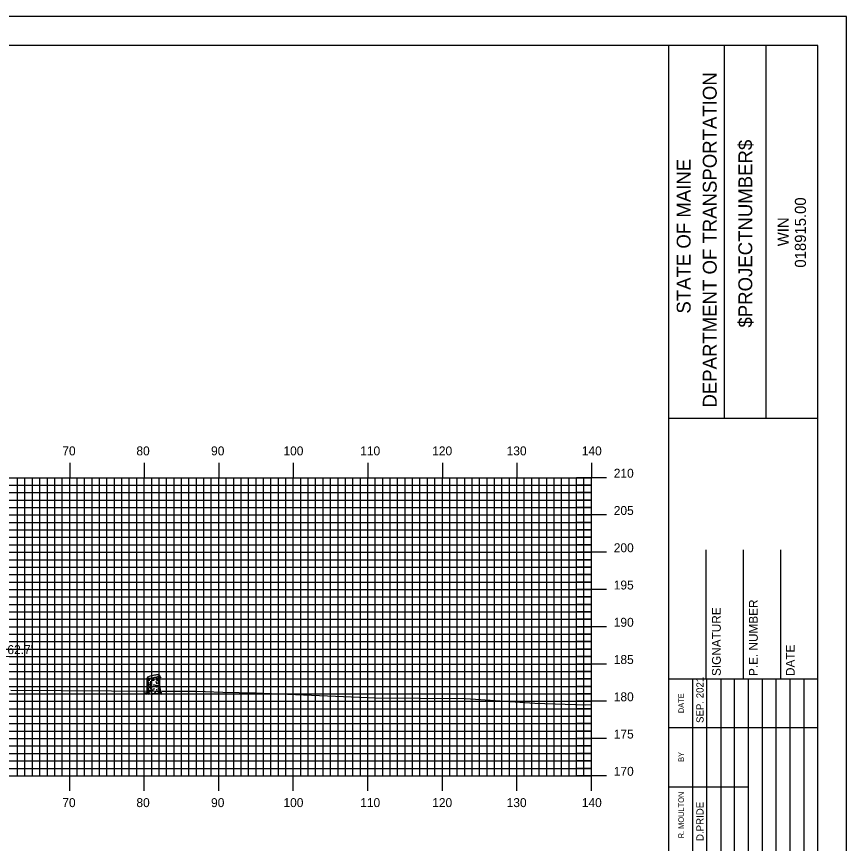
# Model space of a CAD drawing. Extents: x 1808619 to 1808962, y 442591 to 442811.
# Drawn here: x 1808847.7 to 1808959, y 442699.6 to 442810.5 of the extents above; entities that cross this region are included whole.
import ezdxf

# ---------------------------------------------------------------- set-up
doc = ezdxf.new("R2010")
doc.units = 0
for name, color, linetype in [('BORDER', 7, 'Continuous'), ('D_Text_Standard', 7, 'Continuous'), ('H_V ANNOTATION', 7, 'Continuous'), ('M_Trees_Conifer_Pay', 7, 'Continuous'), ('MAJOR', 7, 'Continuous'), ('MINOR', 7, 'Continuous'), ('PLOT BOUNDARY', 7, 'Continuous'), ('S_Roadway_Centerline', 7, 'Continuous')]:
    doc.layers.add(name, color=color, linetype=linetype)

msp = doc.modelspace()

# ---------------------------------------------------------------- linework, layer by layer
at = {"layer": 'BORDER'}
for p, q in [((1808935.21, 442596.67), (1808935.21, 442806.67)), ((1808942.67, 442756.66), (1808942.67, 442806.66)), ((1808948.26, 442756.66), (1808948.26, 442806.66)), ((1808935.21, 442756.65), (1808955.21, 442756.65)), ((1808940.21, 442721.67), (1808940.21, 442738.97)), ((1808945.21, 442721.67), (1808945.21, 442738.97)), ((1808950.21, 442721.67), (1808950.21, 442738.97)), ((1808935.21, 442721.67), (1808955.21, 442721.67))]:
    msp.add_line(p, q, dxfattribs=at)
msp.add_lwpolyline([(1808635.21, 442596.67), (1808955.21, 442596.67), (1808955.21, 442806.67), (1808635.21, 442806.67)], close=True, dxfattribs=at)
for points in [[(1808938.44, 442715.17), (1808938.44, 442721.67)], [(1808940.31, 442686.68), (1808940.31, 442721.67)], [(1808942.17, 442721.67), (1808942.17, 442686.68)], [(1808944.03, 442686.68), (1808944.03, 442721.67)], [(1808945.9, 442686.68), (1808945.9, 442721.67)], [(1808947.76, 442686.68), (1808947.76, 442721.67)], [(1808949.62, 442686.68), (1808949.62, 442721.67)], [(1808951.49, 442686.68), (1808951.49, 442721.67)], [(1808953.35, 442686.68), (1808953.35, 442721.67)], [(1808938.44, 442686.68), (1808938.44, 442720.26)], [(1808935.21, 442715.17), (1808955.21, 442715.17)], [(1808935.21, 442707.17), (1808938.44, 442707.17)], [(1808938.44, 442707.17), (1808945.89, 442707.17)]]:
    msp.add_lwpolyline(points, dxfattribs=at)
at = {"layer": 'M_Trees_Conifer_Pay'}
for p, q in [((1808866.82, 442722.09), (1808866.82, 442721.93)), ((1808866.89, 442720.52), (1808866.89, 442722.16)), ((1808865.22, 442720.11), (1808865.22, 442721.83)), ((1808865.27, 442721.79), (1808865.27, 442721.32)), ((1808865.27, 442721.25), (1808865.27, 442720.95)), ((1808865.33, 442721.78), (1808865.33, 442721.68)), ((1808865.33, 442721.61), (1808865.33, 442721.4)), ((1808865.33, 442721.34), (1808865.33, 442721.15)), ((1808865.33, 442721.1), (1808865.33, 442720.76)), ((1808865.45, 442721.77), (1808865.45, 442721.54)), ((1808865.45, 442721.5), (1808865.45, 442721.42)), ((1808865.45, 442721.02), (1808865.45, 442720.88)), ((1808865.67, 442721.79), (1808865.67, 442721.62)), ((1808865.67, 442721.39), (1808865.67, 442721.15)), ((1808866.08, 442721.56), (1808866.08, 442721.46)), ((1808866.47, 442721.83), (1808866.47, 442721.63)), ((1808866.47, 442721.58), (1808866.47, 442721.49)), ((1808866.47, 442721.14), (1808866.47, 442721.03)), ((1808866.7, 442722.03), (1808866.7, 442721.81)), ((1808866.7, 442721.72), (1808866.7, 442721.67)), ((1808866.76, 442721.53), (1808866.7, 442721.47)), ((1808866.7, 442721.33), (1808866.7, 442721.2)), ((1808866.7, 442721.09), (1808866.7, 442720.98)), ((1808866.82, 442721.86), (1808866.82, 442721.73)), ((1808866.82, 442721.54), (1808866.82, 442721.21)), ((1808866.82, 442721.17), (1808866.82, 442721.01)), ((1808866.82, 442720.96), (1808866.82, 442720.75)), ((1808865.27, 442720.9), (1808865.27, 442720.41)), ((1808865.27, 442720.35), (1808865.27, 442720.11)), ((1808865.33, 442720.71), (1808865.33, 442720.57)), ((1808865.33, 442720.47), (1808865.33, 442720.1)), ((1808865.45, 442720.61), (1808865.45, 442720.47)), ((1808865.45, 442720.21), (1808865.45, 442720.11)), ((1808865.67, 442720.9), (1808865.67, 442720.75)), ((1808865.67, 442720.71), (1808865.67, 442720.54)), ((1808865.67, 442720.26), (1808865.67, 442720.11)), ((1808866.08, 442720.95), (1808866.08, 442720.87)), ((1808866.08, 442720.85), (1808866.08, 442720.7)), ((1808866.08, 442720.41), (1808866.08, 442720.25)), ((1808866.47, 442720.67), (1808866.47, 442720.52)), ((1808866.47, 442720.29), (1808866.47, 442720.2)), ((1808866.7, 442720.85), (1808866.7, 442720.7)), ((1808866.7, 442720.48), (1808866.7, 442720.31)), ((1808866.82, 442720.71), (1808866.82, 442720.64)), ((1808866.82, 442720.6), (1808866.82, 442720.43)), ((1808865.45, 442719.71), (1808865.62, 442719.78)), ((1808865.89, 442719.65), (1808865.77, 442719.71))]:
    msp.add_line(p, q, dxfattribs=at)
for points in [[(1808865.4, 442721.13), (1808865.4, 442721.23), (1808865.44, 442721.2), (1808865.44, 442721.11)], [(1808866.67, 442721.62), (1808866.64, 442721.54), (1808866.64, 442721.47), (1808866.67, 442721.41)], [(1808866.7, 442721.66), (1808866.74, 442721.59), (1808866.79, 442721.64), (1808866.85, 442721.71), (1808866.94, 442721.9), (1808867, 442721.95), (1808867.03, 442721.96)], [(1808866.72, 442721.41), (1808866.76, 442721.53), (1808866.82, 442721.65), (1808866.85, 442721.72), (1808866.92, 442721.86)], [(1808866.93, 442721.89), (1808867.01, 442721.9), (1808867.08, 442721.8)], [(1808866.89, 442720.52), (1808866.94, 442720.25), (1808866.96, 442719.98), (1808867.01, 442719.85), (1808867.15, 442719.82), (1808866.92, 442719.79), (1808866.92, 442719.79), (1808866.92, 442719.74), (1808867.17, 442719.64), (1808866.9, 442719.66), (1808866.54, 442719.68), (1808866.22, 442719.67), (1808866.23, 442719.75), (1808866.08, 442719.67), (1808865.89, 442719.65), (1808865.92, 442719.58), (1808865.65, 442719.62), (1808865.43, 442719.6), (1808865.14, 442719.61), (1808865.42, 442719.67), (1808865.45, 442719.71), (1808865.29, 442719.77), (1808865.06, 442719.78), (1808864.81, 442719.78), (1808865.16, 442719.84), (1808865.2, 442719.92), (1808865.22, 442720.11)], [(1808865.27, 442720.06), (1808865.25, 442719.98), (1808865.23, 442719.89)], [(1808865.35, 442720.04), (1808865.36, 442719.92), (1808865.3, 442719.83), (1808865.29, 442719.77)], [(1808865.51, 442720.06), (1808865.51, 442719.93), (1808865.42, 442719.83)], [(1808865.74, 442719.82), (1808865.81, 442719.92), (1808865.83, 442720.06)], [(1808866.23, 442719.75), (1808866.3, 442719.9), (1808866.31, 442720)], [(1808866.48, 442720.12), (1808866.49, 442720), (1808866.56, 442719.95)], [(1808866.54, 442720.73), (1808866.55, 442720.66), (1808866.6, 442720.67), (1808866.59, 442720.83)], [(1808866.76, 442719.73), (1808866.74, 442719.87), (1808866.67, 442720)], [(1808866.71, 442720.23), (1808866.79, 442720.12), (1808866.79, 442719.95), (1808866.92, 442719.79)], [(1808866.81, 442720.37), (1808866.82, 442720.23), (1808866.87, 442720.16), (1808866.88, 442719.96)]]:
    msp.add_lwpolyline(points, dxfattribs=at)
for centre, radius, start, end in [((1808867.08, 442717.06), 5.18, 101.7194, 108.0594), ((1808867.08, 442717.06), 5.18, 95.3794, 101.7194), ((1808866.67, 442721.42), 0.802, 79.2194, 95.3794), ((1808866.39, 442722.77), 0.802, 288.0594, 304.2194), ((1808866.77, 442721.96), 0.251, 71.0501, 79.2194), ((1808866.7, 442722.31), 0.251, 304.2194, 312.3887), ((1808866.83, 442722.12), 0.0817, 56.7194, 71.0501), ((1808866.84, 442722.14), 0.0527, 46.923, 56.7194), ((1808866.81, 442722.19), 0.0817, 312.3887, 326.7194), ((1808866.86, 442722.16), 0.0264, 23.4074, 34.2194), ((1808866.86, 442722.16), 0.0314, 34.2194, 46.923), ((1808866.84, 442722.17), 0.0527, 326.7194, 336.5158), ((1808866.87, 442722.16), 0.0226, 11.7194, 23.4074), ((1808866.87, 442722.16), 0.0226, 0.0315, 11.7194), ((1808866.86, 442722.16), 0.0314, 336.5158, 349.2194), ((1808866.86, 442722.16), 0.0264, 349.2194, 0.0315), ((1808865.26, 442721.83), 0.0314, 156.5158, 169.2194), ((1808865.25, 442721.83), 0.0264, 169.2194, 180.0315), ((1808865.25, 442721.83), 0.0226, 180.0315, 191.7194), ((1808865.25, 442721.83), 0.0226, 191.7194, 203.4074), ((1808865.26, 442721.65), 0.0334, 163.9485, 180), ((1808865.26, 442721.65), 0.0334, 180, 196.0515), ((1808865.27, 442721.65), 0.0441, 196.0515, 210), ((1808865.26, 442721.2), 0.0334, 163.9485, 180), ((1808865.26, 442721.2), 0.0334, 180, 196.0515), ((1808865.27, 442721.2), 0.0441, 196.0515, 210), ((1808865.26, 442720.99), 0.0334, 163.9485, 180), ((1808865.26, 442720.99), 0.0334, 180, 196.0515), ((1808865.27, 442720.99), 0.0441, 196.0515, 210), ((1808865.3, 442721.8), 0.0817, 132.3887, 146.7194), ((1808865.27, 442721.82), 0.0527, 146.7194, 156.5158), ((1808865.25, 442721.83), 0.0264, 203.4074, 214.2194), ((1808865.25, 442721.83), 0.0314, 214.2194, 226.923), ((1808865.27, 442721.85), 0.0527, 226.923, 236.7194), ((1808865.28, 442721.66), 0.0624, 210, 228.7494), ((1808865.28, 442721.21), 0.0624, 210, 228.7494), ((1808865.28, 442721), 0.0624, 210, 228.7494), ((1808865.41, 442721.68), 0.251, 124.2194, 132.3887), ((1808865.28, 442721.87), 0.0817, 236.7194, 251.0501), ((1808865.35, 442721.74), 0.172, 228.7494, 240), ((1808865.35, 442721.3), 0.172, 228.7494, 240), ((1808865.35, 442721.09), 0.172, 228.7494, 240), ((1808865.34, 442722.03), 0.251, 251.0501, 259.2194), ((1808865.72, 442721.22), 0.802, 108.0594, 124.2194), ((1808865.55, 442722.09), 0.571, 240, 240.3367), ((1808865.56, 442721.88), 0.571, 240, 247.0587), ((1808865.55, 442721.64), 0.571, 240, 240.3367), ((1808865.44, 442722.57), 0.802, 259.2194, 275.3794), ((1808865.55, 442722.09), 0.571, 246.8597, 257.9846), ((1808865.03, 442726.93), 5.18, 275.3794, 281.7194), ((1808866.05, 442725.16), 4.12, 264.081, 266.6676), ((1808866.06, 442725.84), 4.12, 264.6955, 266.7331), ((1808866.05, 442725.61), 4.12, 268.0751, 270), ((1808866.05, 442725.61), 4.12, 270, 270.3581), ((1808865.03, 442726.93), 5.18, 281.7194, 288.0594), ((1808866.06, 442725.39), 4.12, 273.7052, 275.9504), ((1808866.05, 442725.61), 4.12, 275.7849, 277.0558), ((1808866.06, 442725.84), 4.12, 276.238, 278.1032), ((1808866.05, 442725.16), 4.12, 277.6125, 278.1032), ((1808866.56, 442722.32), 0.571, 278.1032, 284.3667), ((1808866.56, 442721.64), 0.571, 278.1032, 286.9296), ((1808866.56, 442722.48), 0.571, 284.4317, 292.4132), ((1808866.56, 442721.88), 0.571, 284.4493, 297.0429), ((1808866.56, 442722.32), 0.571, 297.0237, 300), ((1808866.56, 442721.64), 0.571, 297.1896, 300), ((1808866.76, 442722.13), 0.172, 300, 311.2506), ((1808866.76, 442721.98), 0.172, 300, 311.2506), ((1808866.75, 442721.3), 0.172, 300, 311.2506), ((1808866.75, 442721.09), 0.172, 300, 311.2506), ((1808866.83, 442722.05), 0.0624, 311.2506, 330), ((1808866.83, 442721.89), 0.0624, 311.2506, 330), ((1808866.83, 442721.21), 0.0624, 311.2506, 330), ((1808866.83, 442721), 0.0624, 311.2506, 330), ((1808866.84, 442722.04), 0.0441, 330, 343.9485), ((1808866.84, 442721.88), 0.0441, 330, 343.9485), ((1808866.84, 442721.2), 0.0441, 330, 343.9485), ((1808866.84, 442720.99), 0.0441, 330, 343.9485), ((1808866.85, 442722.04), 0.0334, 343.9485, 354.2151), ((1808866.85, 442721.88), 0.0334, 343.9485, 354.2151), ((1808866.85, 442721.44), 0.0334, 343.9485, 354.2151), ((1808866.85, 442721.2), 0.0334, 343.9485, 354.2151), ((1808866.85, 442720.99), 0.0334, 343.9485, 354.2151), ((1808865.26, 442720.76), 0.0334, 163.9485, 180), ((1808865.26, 442720.76), 0.0334, 180, 196.0515), ((1808865.27, 442720.76), 0.0441, 196.0515, 210), ((1808865.26, 442720.56), 0.0334, 163.9485, 180), ((1808865.26, 442720.36), 0.0334, 163.9485, 180), ((1808865.26, 442720.36), 0.0334, 180, 196.0515), ((1808865.27, 442720.36), 0.0441, 196.0515, 210), ((1808865.26, 442720.14), 0.0334, 163.9485, 180), ((1808865.26, 442720.14), 0.0334, 180, 196.0515), ((1808865.27, 442720.14), 0.0441, 196.0515, 210), ((1808865.28, 442720.77), 0.0624, 210, 228.7494), ((1808865.28, 442720.37), 0.0624, 210, 228.7494), ((1808865.28, 442720.15), 0.0624, 210, 228.7494), ((1808865.35, 442720.85), 0.172, 228.7494, 240), ((1808865.35, 442720.46), 0.172, 228.7494, 240), ((1808865.35, 442720.24), 0.172, 228.7494, 240), ((1808865.55, 442721.43), 0.571, 240, 246.8597), ((1808865.55, 442721.19), 0.571, 240, 246.8597), ((1808865.54, 442721), 0.571, 241.2369, 248.0268), ((1808865.55, 442720.8), 0.571, 240, 246.8597), ((1808865.55, 442720.58), 0.571, 240, 244.5314), ((1808865.55, 442721.43), 0.571, 259.2707, 261.8968), ((1808866.05, 442724.95), 4.12, 261.8968, 263.1474), ((1808866.05, 442724.1), 4.12, 262.4438, 263.512), ((1808866.05, 442724.51), 4.12, 263.4991, 265.8397), ((1808866.05, 442724.71), 4.12, 264.716, 266.3193), ((1808866.05, 442724.32), 4.12, 267.8117, 270), ((1808866.05, 442724.95), 4.12, 270, 270.3581), ((1808866.05, 442724.32), 4.12, 270, 270.1328), ((1808866.05, 442724.95), 4.12, 273.1493, 275.4569), ((1808866.05, 442724.32), 4.12, 275.7849, 276.7896), ((1808866.05, 442724.1), 4.12, 277.3684, 278.1032), ((1808866.56, 442720.58), 0.571, 278.1032, 281.637), ((1808866.56, 442721.19), 0.571, 285.3983, 297.1896), ((1808866.56, 442721), 0.571, 289.2907, 300), ((1808866.56, 442720.8), 0.571, 288.5067, 297.2721), ((1808866.56, 442721.43), 0.571, 297.1896, 300), ((1808866.75, 442720.65), 0.172, 300, 311.2506), ((1808866.75, 442720.24), 0.172, 300, 311.2506), ((1808866.83, 442720.57), 0.0624, 311.2506, 330), ((1808866.83, 442720.15), 0.0624, 311.2506, 330), ((1808866.84, 442720.56), 0.0441, 330, 343.9485), ((1808866.84, 442720.14), 0.0441, 330, 343.9485), ((1808866.85, 442720.56), 0.0334, 343.9485, 354.2151), ((1808866.85, 442720.14), 0.0334, 343.9485, 354.2151)]:
    msp.add_arc(centre, radius, start, end, dxfattribs=at)
at = {"layer": 'MAJOR'}
for p, q in [((1808854.81, 442750.67), (1808854.81, 442748.67)), ((1808864.81, 442750.67), (1808864.81, 442748.67)), ((1808874.81, 442750.67), (1808874.81, 442748.67)), ((1808884.81, 442750.67), (1808884.81, 442748.67)), ((1808894.81, 442750.67), (1808894.81, 442748.67)), ((1808904.81, 442750.67), (1808904.81, 442748.67)), ((1808914.81, 442750.67), (1808914.81, 442748.67)), ((1808924.81, 442750.67), (1808924.81, 442748.67)), ((1808644.81, 442748.67), (1808924.81, 442748.67)), ((1808644.81, 442748.67), (1808924.81, 442748.67)), ((1808854.81, 442708.67), (1808854.81, 442748.67)), ((1808864.81, 442708.67), (1808864.81, 442748.67)), ((1808874.81, 442708.67), (1808874.81, 442748.67)), ((1808884.81, 442708.67), (1808884.81, 442748.67)), ((1808894.81, 442708.67), (1808894.81, 442748.67)), ((1808904.81, 442708.67), (1808904.81, 442748.67)), ((1808914.81, 442708.67), (1808914.81, 442748.67)), ((1808926.82, 442748.67), (1808922.81, 442748.67)), ((1808924.81, 442708.67), (1808924.81, 442748.67)), ((1808924.81, 442708.67), (1808924.81, 442748.67)), ((1808644.81, 442743.67), (1808924.81, 442743.67)), ((1808926.82, 442743.67), (1808922.81, 442743.67)), ((1808644.81, 442738.67), (1808924.81, 442738.67)), ((1808926.82, 442738.67), (1808922.81, 442738.67)), ((1808644.81, 442733.67), (1808924.81, 442733.67)), ((1808926.82, 442733.67), (1808922.81, 442733.67)), ((1808644.81, 442728.67), (1808924.81, 442728.67)), ((1808926.82, 442728.67), (1808922.81, 442728.67)), ((1808644.81, 442723.67), (1808924.81, 442723.67)), ((1808926.82, 442723.67), (1808922.81, 442723.67)), ((1808644.81, 442718.67), (1808924.81, 442718.67)), ((1808926.82, 442718.67), (1808922.81, 442718.67)), ((1808644.81, 442713.67), (1808924.81, 442713.67)), ((1808926.82, 442713.67), (1808922.81, 442713.67)), ((1808644.81, 442708.67), (1808924.81, 442708.67)), ((1808644.81, 442708.67), (1808924.81, 442708.67)), ((1808854.81, 442706.66), (1808854.81, 442708.67)), ((1808864.81, 442706.66), (1808864.81, 442708.67)), ((1808874.81, 442706.66), (1808874.81, 442708.67)), ((1808884.81, 442706.66), (1808884.81, 442708.67)), ((1808894.81, 442706.66), (1808894.81, 442708.67)), ((1808904.81, 442706.66), (1808904.81, 442708.67)), ((1808914.81, 442706.66), (1808914.81, 442708.67)), ((1808926.82, 442708.67), (1808922.81, 442708.67)), ((1808924.81, 442706.66), (1808924.81, 442708.67))]:
    msp.add_line(p, q, dxfattribs=at)
at = {"layer": 'MINOR'}
for p, q in [((1808847.81, 442708.67), (1808847.81, 442748.67)), ((1808848.81, 442708.67), (1808848.81, 442748.67)), ((1808849.81, 442708.67), (1808849.81, 442748.67)), ((1808850.81, 442708.67), (1808850.81, 442748.67)), ((1808851.81, 442708.67), (1808851.81, 442748.67)), ((1808852.81, 442708.67), (1808852.81, 442748.67)), ((1808853.81, 442708.67), (1808853.81, 442748.67)), ((1808855.81, 442708.67), (1808855.81, 442748.67)), ((1808856.81, 442708.67), (1808856.81, 442748.67)), ((1808857.81, 442708.67), (1808857.81, 442748.67)), ((1808858.81, 442708.67), (1808858.81, 442748.67)), ((1808859.81, 442708.67), (1808859.81, 442748.67)), ((1808860.81, 442708.67), (1808860.81, 442748.67)), ((1808861.81, 442708.67), (1808861.81, 442748.67)), ((1808862.81, 442708.67), (1808862.81, 442748.67)), ((1808863.81, 442708.67), (1808863.81, 442748.67)), ((1808865.81, 442708.67), (1808865.81, 442748.67)), ((1808866.81, 442708.67), (1808866.81, 442748.67)), ((1808867.81, 442708.67), (1808867.81, 442748.67)), ((1808868.81, 442708.67), (1808868.81, 442748.67)), ((1808869.81, 442708.67), (1808869.81, 442748.67)), ((1808870.81, 442708.67), (1808870.81, 442748.67)), ((1808871.81, 442708.67), (1808871.81, 442748.67)), ((1808872.81, 442708.67), (1808872.81, 442748.67)), ((1808873.81, 442708.67), (1808873.81, 442748.67)), ((1808875.81, 442708.67), (1808875.81, 442748.67)), ((1808876.81, 442708.67), (1808876.81, 442748.67)), ((1808877.81, 442708.67), (1808877.81, 442748.67)), ((1808878.81, 442708.67), (1808878.81, 442748.67)), ((1808879.81, 442708.67), (1808879.81, 442748.67)), ((1808880.81, 442708.67), (1808880.81, 442748.67)), ((1808881.81, 442708.67), (1808881.81, 442748.67)), ((1808882.81, 442708.67), (1808882.81, 442748.67)), ((1808883.81, 442708.67), (1808883.81, 442748.67)), ((1808885.81, 442708.67), (1808885.81, 442748.67)), ((1808886.81, 442708.67), (1808886.81, 442748.67)), ((1808887.81, 442708.67), (1808887.81, 442748.67)), ((1808888.81, 442708.67), (1808888.81, 442748.67)), ((1808889.81, 442708.67), (1808889.81, 442748.67)), ((1808890.81, 442708.67), (1808890.81, 442748.67)), ((1808891.81, 442708.67), (1808891.81, 442748.67)), ((1808892.81, 442708.67), (1808892.81, 442748.67)), ((1808893.81, 442708.67), (1808893.81, 442748.67)), ((1808895.81, 442708.67), (1808895.81, 442748.67)), ((1808896.81, 442708.67), (1808896.81, 442748.67)), ((1808897.81, 442708.67), (1808897.81, 442748.67)), ((1808898.81, 442708.67), (1808898.81, 442748.67)), ((1808899.81, 442708.67), (1808899.81, 442748.67)), ((1808900.81, 442708.67), (1808900.81, 442748.67)), ((1808901.81, 442708.67), (1808901.81, 442748.67)), ((1808902.81, 442708.67), (1808902.81, 442748.67)), ((1808903.81, 442708.67), (1808903.81, 442748.67)), ((1808905.81, 442708.67), (1808905.81, 442748.67)), ((1808906.81, 442708.67), (1808906.81, 442748.67)), ((1808907.81, 442708.67), (1808907.81, 442748.67)), ((1808908.81, 442708.67), (1808908.81, 442748.67)), ((1808909.81, 442708.67), (1808909.81, 442748.67)), ((1808910.81, 442708.67), (1808910.81, 442748.67)), ((1808911.81, 442708.67), (1808911.81, 442748.67)), ((1808912.81, 442708.67), (1808912.81, 442748.67)), ((1808913.81, 442708.67), (1808913.81, 442748.67)), ((1808915.81, 442708.67), (1808915.81, 442748.67)), ((1808916.81, 442708.67), (1808916.81, 442748.67)), ((1808917.81, 442708.67), (1808917.81, 442748.67)), ((1808918.81, 442708.67), (1808918.81, 442748.67)), ((1808919.81, 442708.67), (1808919.81, 442748.67)), ((1808920.81, 442708.67), (1808920.81, 442748.67)), ((1808921.81, 442708.67), (1808921.81, 442748.67)), ((1808922.81, 442708.67), (1808922.81, 442748.67)), ((1808923.81, 442708.67), (1808923.81, 442748.67)), ((1808644.81, 442747.67), (1808924.81, 442747.67)), ((1808644.81, 442746.67), (1808924.81, 442746.67)), ((1808924.81, 442747.67), (1808922.81, 442747.67)), ((1808924.81, 442746.67), (1808922.81, 442746.67)), ((1808644.81, 442745.67), (1808924.81, 442745.67)), ((1808924.81, 442745.67), (1808922.81, 442745.67)), ((1808644.81, 442744.67), (1808924.81, 442744.67)), ((1808924.81, 442744.67), (1808922.81, 442744.67)), ((1808644.81, 442742.67), (1808924.81, 442742.67)), ((1808924.81, 442742.67), (1808922.81, 442742.67)), ((1808644.81, 442741.67), (1808924.81, 442741.67)), ((1808924.81, 442741.67), (1808922.81, 442741.67)), ((1808644.81, 442740.67), (1808924.81, 442740.67)), ((1808924.81, 442740.67), (1808922.81, 442740.67)), ((1808644.81, 442739.67), (1808924.81, 442739.67)), ((1808924.81, 442739.67), (1808922.81, 442739.67)), ((1808644.81, 442737.67), (1808924.81, 442737.67)), ((1808924.81, 442737.67), (1808922.81, 442737.67)), ((1808644.81, 442736.67), (1808924.81, 442736.67)), ((1808924.81, 442736.67), (1808922.81, 442736.67)), ((1808644.81, 442735.67), (1808924.81, 442735.67)), ((1808924.81, 442735.67), (1808922.81, 442735.67)), ((1808644.81, 442734.67), (1808924.81, 442734.67)), ((1808924.81, 442734.67), (1808922.81, 442734.67)), ((1808644.81, 442732.67), (1808924.81, 442732.67)), ((1808924.81, 442732.67), (1808922.81, 442732.67)), ((1808644.81, 442731.67), (1808924.81, 442731.67)), ((1808924.81, 442731.67), (1808922.81, 442731.67)), ((1808644.81, 442730.67), (1808924.81, 442730.67)), ((1808924.81, 442730.67), (1808922.81, 442730.67)), ((1808644.81, 442729.67), (1808924.81, 442729.67)), ((1808924.81, 442729.67), (1808922.81, 442729.67)), ((1808644.81, 442727.67), (1808924.81, 442727.67)), ((1808924.81, 442727.67), (1808922.81, 442727.67)), ((1808644.81, 442726.67), (1808924.81, 442726.67)), ((1808924.81, 442726.67), (1808922.81, 442726.67)), ((1808644.81, 442725.67), (1808924.81, 442725.67)), ((1808924.81, 442725.67), (1808922.81, 442725.67)), ((1808644.81, 442724.67), (1808924.81, 442724.67)), ((1808924.81, 442724.67), (1808922.81, 442724.67)), ((1808644.81, 442722.67), (1808924.81, 442722.67)), ((1808924.81, 442722.67), (1808922.81, 442722.67)), ((1808644.81, 442721.67), (1808924.81, 442721.67)), ((1808924.81, 442721.67), (1808922.81, 442721.67)), ((1808644.81, 442720.67), (1808924.81, 442720.67)), ((1808924.81, 442720.67), (1808922.81, 442720.67)), ((1808644.81, 442719.67), (1808924.81, 442719.67)), ((1808924.81, 442719.67), (1808922.81, 442719.67)), ((1808644.81, 442717.67), (1808924.81, 442717.67)), ((1808924.81, 442717.67), (1808922.81, 442717.67)), ((1808644.81, 442716.67), (1808924.81, 442716.67)), ((1808924.81, 442716.67), (1808922.81, 442716.67)), ((1808644.81, 442715.67), (1808924.81, 442715.67)), ((1808924.81, 442715.67), (1808922.81, 442715.67)), ((1808644.81, 442714.67), (1808924.81, 442714.67)), ((1808924.81, 442714.67), (1808922.81, 442714.67)), ((1808644.81, 442712.67), (1808924.81, 442712.67)), ((1808924.81, 442712.67), (1808922.81, 442712.67)), ((1808644.81, 442711.67), (1808924.81, 442711.67)), ((1808924.81, 442711.67), (1808922.81, 442711.67)), ((1808644.81, 442710.67), (1808924.81, 442710.67)), ((1808924.81, 442710.67), (1808922.81, 442710.67)), ((1808644.81, 442709.67), (1808924.81, 442709.67)), ((1808924.81, 442709.67), (1808922.81, 442709.67))]:
    msp.add_line(p, q, dxfattribs=at)
at = {"layer": 'PLOT BOUNDARY'}
msp.add_lwpolyline([(1808619.02, 442590.55), (1808959.02, 442590.55), (1808959.02, 442810.55), (1808619.02, 442810.55)], close=True, dxfattribs=at)
at = {"layer": 'S_Roadway_Centerline'}
msp.add_lwpolyline([(1808846.93, 442720.15), (1808867.17, 442720.02), (1808871.76, 442720.02), (1808875.36, 442719.91), (1808879.75, 442719.8), (1808895.84, 442719.14), (1808907.93, 442719.04), (1808917.22, 442718.43), (1808924.03, 442718.2), (1808924.81, 442718.23)], dxfattribs=at)

# ---------------------------------------------------------------- texts
at = {"layer": 'BORDER'}
for s, height, p in [('DEPARTMENT OF TRANSPORTATION', 1.8635, (1808941.62, 442758.08)), ('$PROJECTNUMBER$', 1.8635, (1808946.39, 442768.82)), ('STATE OF MAINE', 1.8635, (1808938.12, 442770.69)), ('018915.00', 1.491, (1808953.6, 442776.86)), ('WIN', 1.491, (1808951.28, 442779.73)), ('P.E. NUMBER', 1.1811, (1808947.13, 442722.06)), ('SIGNATURE', 1.181, (1808942.17, 442722.06)), ('DATE', 1.181, (1808952.09, 442722.06)), ('SEP. 2021', 0.969, (1808939.86, 442715.76)), ('DATE', 0.743, (1808937.22, 442717.08)), ('BY', 0.743, (1808937.22, 442710.54)), ('R. MOULTON', 0.745, (1808937.22, 442700.28)), ('D.PRIDE', 0.969, (1808939.86, 442699.92))]:
    msp.add_text(s, height=height, rotation=90, dxfattribs=at).set_placement(p)
at = {"layer": 'D_Text_Standard'}
msp.add_text("62.7'", height=1.2, dxfattribs=at).set_placement((1808846.45, 442725))
at = {"layer": 'H_V ANNOTATION'}
for s, p in [('70', (1808853.82, 442751.67)), ('80', (1808863.76, 442751.67)), ('90', (1808873.78, 442751.67)), ('100', (1808883.49, 442751.67)), ('110', (1808893.79, 442751.67)), ('120', (1808903.45, 442751.67)), ('130', (1808913.44, 442751.67)), ('140', (1808923.52, 442751.67)), ('210', (1808927.81, 442748.67)), ('205', (1808927.81, 442743.67)), ('200', (1808927.81, 442738.67)), ('195', (1808927.81, 442733.67)), ('190', (1808927.81, 442728.67)), ('185', (1808927.81, 442723.67)), ('180', (1808927.81, 442718.67)), ('175', (1808927.81, 442713.67)), ('170', (1808927.81, 442708.67)), ('70', (1808853.82, 442704.47)), ('80', (1808863.76, 442704.47)), ('90', (1808873.78, 442704.47)), ('100', (1808883.49, 442704.47)), ('110', (1808893.79, 442704.47)), ('120', (1808903.45, 442704.47)), ('130', (1808913.44, 442704.47)), ('140', (1808923.52, 442704.47))]:
    msp.add_text(s, height=1.2, dxfattribs=at).set_placement(p)

doc.saveas('drawing.dxf')
